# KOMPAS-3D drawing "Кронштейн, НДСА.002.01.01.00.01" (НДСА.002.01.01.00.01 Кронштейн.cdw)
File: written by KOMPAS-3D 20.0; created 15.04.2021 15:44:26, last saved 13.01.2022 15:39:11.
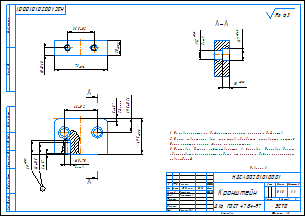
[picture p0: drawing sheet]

Sheet 1: A3, landscape

Document properties: Автор: 111; Полное имя файла: C:\Users\korychko\Desktop\PLM\НДСА.002.01.01.00.01 Кронштейн.cdw; Параметр неуказанной шероховатости: Ra 6,3; PLM_CDWXDTO: <item xmlns="http://appius.ru/pdm" xmlns:xs="http://www.w3.org/2001/XMLSchema" xmlns:xsi="http://www.w3.org/2001/XMLSchema-instance" xsi:type="item">  <element xmlns:d2p1="http://v8.1c.ru/8.1/data/enterprise/current-config" xsi:type="d2p1:CatalogRef.aps_Элемен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; Масса: 0.178026; PDM_DOCXDTO: <item xmlns="http://appius.ru/pdm" xmlns:xs="http://www.w3.org/2001/XMLSchema" xmlns:xsi="http://www.w3.org/2001/XMLSchema-instance" xsi:type="item">  <element xmlns:d2p1="http://v8.1c.ru/8.1/data/enterprise/current-config" xsi:type="d2p1:CatalogRef.aps_Элемен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; PDM_ITEMXDTO: <item xmlns="http://appius.ru/pdm" xmlns:xs="http://www.w3.org/2001/XMLSchema" xmlns:xsi="http://www.w3.org/2001/XMLSchema-instance" xsi:type="item">  <element xmlns:d2p1="http://v8.1c.ru/8.1/data/enterprise/current-config" xsi:type="d2p1:CatalogRef.aps_Элемен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; PDM_DRAWINGXDTO: <item xmlns="http://appius.ru/pdm" xmlns:xs="http://www.w3.org/2001/XMLSchema" xmlns:xsi="http://www.w3.org/2001/XMLSchema-instance" xsi:type="item">  <element xmlns:d2p1="http://v8.1c.ru/8.1/data/enterprise/current-config" xsi:type="d2p1:CatalogRef.aps_Элемен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

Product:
- Part/product: Кронштейн  | designation НДСА.002.01.01.00.01
    Материал: Д16  ГОСТ 4784-97 (density 2800 kg/m3)
    Масса: 0.178026
    additional columns: <item xmlns="http://appius.ru/pdm" xmlns:xs="http://www.w3.org/2001/XMLSchema" x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; <item xmlns="http://appius.ru/pdm" xmlns:xs="http://www.w3.org/2001/XMLSchema" x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; <item xmlns="http://appius.ru/pdm" xmlns:xs="http://www.w3.org/2001/XMLSchema" x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
    source file: НДСА.002.01.01.00.01 Кронштейн.cdw

Title block, sheet 1: Наименование: Кронштейн; designation: НДСА.002.01.01.00.01; Материал: Д16  ГОСТ 4784-97; Масса: 0,18; Количество листов документа: 1; organisation: ЭСТО; Форматы листов документа: A3; stored path: C:\Users\s.pischagina\Desktop\PLM\НДСА.002.01.01.00.01 Кронштейн.cdw; Разработал: Пищагина; Проверил: Горностаев; Утвердил: Виноградов; Разработал, date: 15.04.21

Views: Вид 1, Местный разрез 1, Слева, Проекционный вид 3, Разрез А-А
Referenced files in C:\Users\s.pischagina\Desktop\PLM\: НДСА.002.01.01.00.01 Кронштейн.m3d
Referenced files in C:\Users\korychko\Desktop\PLM\: НДСА.002.01.01.00.01 Кронштейн.m3d
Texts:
  Ревизия 1
  Ra 6,3
  Корячко
  НДСА.002.01.01.00.01 Кронштейн
Dimensions and other numbers on the sheet: 46±0,2; 5; 2фаски; 19,5±0,26; 49,5; 1; 16±0,5; 19; -7Н; 8; 2отв; 36,5±0,2; 10±0,18; 20; 73; 12; 17; 1:1; 0,18; 15.04.21; 13.01.2022; 775

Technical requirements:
  На поверхностях не допускается наличие царапин и дефектов.
  После завершения всех процессов обработки произвести очистку.
  После очистки голыми руками не прикасаться.
  Поставка детали осуществляется в упаковке. Упаковка должна
  обеспечивать сохранность изделия от царапин и других механических
  повреждений.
